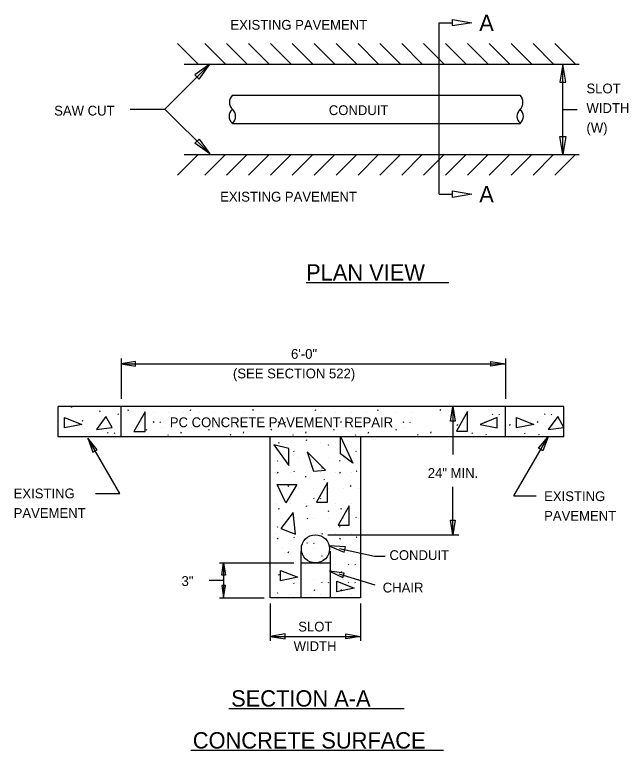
# Model space of a CAD drawing. Extents: x -234.3 to -227.16, y 225.75 to 234.94.
# Drawn here: x -234.204 to -230.444, y 230.43 to 234.938 of the extents above; entities that cross this region are included whole.
import ezdxf

# ---------------------------------------------------------------- set-up
doc = ezdxf.new("R2010")
doc.units = 0
for name, color, linetype in [('Default', 7, 'Continuous'), ('DETL-DIMS', 7, 'Continuous'), ('DETL-LINE', 7, 'Continuous'), ('DETL-NOTE', 7, 'Continuous'), ('DETL-PATT', 7, 'Continuous'), ('DETL-TITL', 7, 'Continuous')]:
    doc.layers.add(name, color=color, linetype=linetype)

msp = doc.modelspace()

# ---------------------------------------------------------------- linework, layer by layer
at = {"layer": 'Default'}
for p, q in [((-233.938, 232.351), (-233.938, 232.536)), ((-233.8555, 232.5297), (-233.8526, 232.5362)), ((-233.6845, 232.5117), (-233.6837, 232.5052)), ((-233.5098, 232.5127), (-233.507, 232.5192)), ((-233.1272, 232.5127), (-233.1243, 232.5192)), ((-232.7446, 232.5127), (-232.7417, 232.5192)), ((-232.3619, 232.5127), (-232.359, 232.5192)), ((-231.9793, 232.5127), (-231.9764, 232.5192)), ((-231.5966, 232.5127), (-231.5938, 232.5192)), ((-230.839, 232.351), (-230.839, 232.536)), ((-233.79, 232.4463), (-233.7871, 232.4528)), ((-233.5717, 232.4926), (-233.5688, 232.4883)), ((-231.2794, 232.491), (-231.2765, 232.4867)), ((-231.2384, 232.4894), (-231.2355, 232.4851)), ((-230.9574, 232.491), (-230.9545, 232.4867)), ((-230.9164, 232.4894), (-230.9135, 232.4851)), ((-233.3552, 232.444), (-233.3523, 232.4397)), ((-233.3142, 232.4424), (-233.3113, 232.4381)), ((-232.9725, 232.444), (-232.9697, 232.4397)), ((-232.9316, 232.4424), (-232.9287, 232.4381)), ((-232.5899, 232.444), (-232.587, 232.4397)), ((-232.5489, 232.4424), (-232.5461, 232.4381)), ((-232.2073, 232.444), (-232.2044, 232.4397)), ((-232.1663, 232.4424), (-232.1634, 232.4381)), ((-231.8246, 232.444), (-231.8217, 232.4397)), ((-231.7837, 232.4424), (-231.7808, 232.4381)), ((-231.4923, 232.4211), (-231.4894, 232.4276)), ((-231.3209, 232.4397), (-231.319, 232.4442)), ((-231.1703, 232.4211), (-231.1674, 232.4276)), ((-230.9998, 232.4377), (-230.997, 232.4442)), ((-233.6354, 232.3776), (-233.6325, 232.3732)), ((-233.5944, 232.3759), (-233.5915, 232.3716)), ((-233.3976, 232.3907), (-233.3948, 232.3972)), ((-233.266, 232.3658), (-233.2631, 232.3614)), ((-233.1855, 232.3742), (-233.1826, 232.3806)), ((-233.015, 232.3907), (-233.0121, 232.3972)), ((-232.8833, 232.3658), (-232.8805, 232.3614)), ((-232.8028, 232.3742), (-232.7999, 232.3806)), ((-232.6324, 232.3907), (-232.6295, 232.3972)), ((-232.5007, 232.3658), (-232.4978, 232.3614)), ((-232.4202, 232.3742), (-232.4173, 232.3806)), ((-232.2497, 232.3907), (-232.2468, 232.3972)), ((-232.1181, 232.3658), (-232.1152, 232.3614)), ((-232.0375, 232.3742), (-232.0347, 232.3806)), ((-231.8671, 232.3907), (-231.8642, 232.3972)), ((-231.7354, 232.3658), (-231.7325, 232.3614)), ((-231.6549, 232.3742), (-231.652, 232.3806)), ((-231.4024, 232.3751), (-231.3995, 232.3708)), ((-231.3174, 232.3673), (-231.3145, 232.363)), ((-231.0804, 232.3751), (-231.0775, 232.3708)), ((-230.9954, 232.3673), (-230.9925, 232.363)), ((-232.5866, 232.3116), (-232.5837, 232.3181)), ((-232.4161, 232.3282), (-232.4132, 232.3346)), ((-232.2844, 232.3032), (-232.2816, 232.2989)), ((-232.4966, 232.2656), (-232.4938, 232.2613)), ((-232.4116, 232.2578), (-232.4088, 232.2535)), ((-232.114, 232.2656), (-232.1111, 232.2613)), ((-232.5961, 232.2067), (-232.5932, 232.2024)), ((-232.2135, 232.2067), (-232.2106, 232.2024)), ((-232.5938, 232.1289), (-232.5909, 232.1354)), ((-232.4939, 232.1429), (-232.4911, 232.1385)), ((-232.3204, 232.1584), (-232.3176, 232.1649)), ((-232.2111, 232.1289), (-232.2082, 232.1354)), ((-232.1113, 232.1429), (-232.1084, 232.1385)), ((-232.4227, 232.1108), (-232.422, 232.1044)), ((-232.31, 232.0918), (-232.3071, 232.0875)), ((-232.5283, 232.0455), (-232.5254, 232.0519)), ((-232.1457, 232.0455), (-232.1428, 232.0519)), ((-232.3736, 231.9768), (-232.3708, 231.9724)), ((-232.3327, 231.9751), (-232.3298, 231.9708)), ((-232.5866, 231.9069), (-232.5837, 231.9134)), ((-232.4161, 231.9234), (-232.4132, 231.9299)), ((-232.2039, 231.9069), (-232.201, 231.9134)), ((-232.2844, 231.8985), (-232.2816, 231.8942)), ((-232.4966, 231.8609), (-232.4938, 231.8565)), ((-232.4116, 231.8531), (-232.4088, 231.8488)), ((-232.114, 231.8609), (-232.1111, 231.8565)), ((-232.5961, 231.802), (-232.5932, 231.7977)), ((-232.2135, 231.802), (-232.2106, 231.7977)), ((-232.5938, 231.7242), (-232.5909, 231.7307)), ((-232.4939, 231.7381), (-232.4911, 231.7338)), ((-232.3204, 231.7537), (-232.3176, 231.7602)), ((-232.2111, 231.7242), (-232.2082, 231.7307)), ((-232.1113, 231.7381), (-232.1084, 231.7338)), ((-232.4145, 231.7029), (-232.4116, 231.6985)), ((-232.3736, 231.7012), (-232.3707, 231.6969)), ((-232.5283, 231.6408), (-232.5254, 231.6472)), ((-232.3253, 231.6246), (-232.3224, 231.6203)), ((-232.1611, 231.5721), (-232.1582, 231.5677)), ((-232.1201, 231.5704), (-232.1172, 231.5661)), ((-232.5866, 231.5022), (-232.5837, 231.5087)), ((-232.2035, 231.5187), (-232.2006, 231.5252)), ((-232.3246, 231.4617), (-232.3217, 231.4574)), ((-232.2836, 231.46), (-232.2807, 231.4557)), ((-232.1611, 231.4617), (-232.1582, 231.4574)), ((-232.1201, 231.46), (-232.1172, 231.4557)), ((-232.4966, 231.4562), (-232.4938, 231.4518)), ((-232.367, 231.4084), (-232.3642, 231.4148)), ((-232.2035, 231.4084), (-232.2006, 231.4148)), ((-232.5961, 231.3973), (-232.5932, 231.393))]:
    msp.add_line(p, q, dxfattribs=at)
at = {"layer": 'DETL-DIMS'}
for p, q in [((-231.6036, 234.8875), (-231.5216, 234.8875)), ((-231.6036, 233.8385), (-231.6036, 234.8875)), ((-233.2846, 234.3595), (-233.0086, 234.6335)), ((-230.8446, 234.0815), (-230.8446, 234.6335)), ((-233.2866, 234.3575), (-233.4966, 234.3575)), ((-233.0086, 234.0855), (-233.2846, 234.3595)), ((-230.7566, 234.3555), (-230.8446, 234.3555)), ((-231.6036, 233.8385), (-231.5216, 233.8385)), ((-233.553, 232.83), (-233.553, 232.584)), ((-231.197, 232.83), (-231.197, 232.584)), ((-233.553, 232.798), (-231.197, 232.798)), ((-231.52, 232.536), (-231.52, 232.242)), ((-233.561, 232.004), (-233.756, 232.342)), ((-231.146, 231.989), (-230.936, 232.351)), ((-231.52, 231.751), (-231.52, 232.045)), ((-233.71, 232.004), (-233.561, 232.004)), ((-231.146, 231.989), (-231.009, 231.989)), ((-232.285, 231.751), (-231.482, 231.751)), ((-232.214, 231.667), (-232, 231.62)), ((-232, 231.62), (-231.934, 231.62)), ((-232.949, 231.578), (-232.493, 231.578)), ((-232.924, 231.578), (-232.924, 231.364)), ((-232.218, 231.511), (-231.997, 231.444)), ((-232.924, 231.471), (-233.013, 231.471)), ((-232.949, 231.364), (-232.675, 231.364)), ((-232.638, 231.33), (-232.638, 231.101)), ((-232.085, 231.33), (-232.085, 231.101)), ((-232.638, 231.128), (-232.085, 231.128))]:
    msp.add_line(p, q, dxfattribs=at)
for points in [[(-231.5216, 234.8685), (-231.5216, 234.9075), (-231.4026, 234.8875)], [(-233.0996, 234.5695), (-233.0736, 234.5435), (-233.0086, 234.6335)], [(-230.8636, 234.5235), (-230.8266, 234.5235), (-230.8446, 234.6335)], [(-233.0996, 234.1495), (-233.0736, 234.1755), (-233.0086, 234.0855)], [(-230.8636, 234.1915), (-230.8266, 234.1915), (-230.8446, 234.0815)], [(-231.5216, 233.8175), (-231.5216, 233.8575), (-231.4026, 233.8375)], [(-233.464, 232.783), (-233.464, 232.813), (-233.553, 232.798)], [(-231.287, 232.783), (-231.287, 232.813), (-231.197, 232.798)], [(-231.505, 232.446), (-231.534, 232.446), (-231.52, 232.536)], [(-233.725, 232.257), (-233.699, 232.272), (-233.756, 232.342)], [(-230.968, 232.266), (-230.994, 232.281), (-230.936, 232.351)], [(-231.534, 231.84), (-231.505, 231.84), (-231.52, 231.751)], [(-232.185, 231.644), (-232.178, 231.676), (-232.279, 231.682)], [(-232.912, 231.503), (-232.936, 231.503), (-232.924, 231.578)], [(-232.194, 231.488), (-232.186, 231.516), (-232.276, 231.528)], [(-232.912, 231.439), (-232.936, 231.439), (-232.924, 231.364)], [(-232.548, 231.113), (-232.548, 231.143), (-232.638, 231.128)], [(-232.175, 231.113), (-232.175, 231.143), (-232.085, 231.128)]]:
    msp.add_lwpolyline(points, close=True, dxfattribs=at)
at = {"layer": 'DETL-LINE'}
for p, q in [((-233.1666, 234.6335), (-230.7446, 234.6335)), ((-232.8706, 234.4435), (-231.1076, 234.4435)), ((-232.8706, 234.2715), (-231.1076, 234.2715)), ((-233.1666, 234.0815), (-230.7446, 234.0815)), ((-230.839, 232.536), (-233.938, 232.536)), ((-233.553, 232.351), (-233.553, 232.536)), ((-231.197, 232.351), (-231.197, 232.536)), ((-230.839, 232.351), (-233.938, 232.351)), ((-232.638, 231.365), (-232.638, 232.351)), ((-232.085, 232.351), (-232.085, 231.365)), ((-232.451, 231.65), (-232.451, 231.365)), ((-232.272, 231.65), (-232.272, 231.365)), ((-232.451, 231.578), (-232.272, 231.578)), ((-232.086, 231.364), (-232.637, 231.364))]:
    msp.add_line(p, q, dxfattribs=at)
msp.add_circle((-232.3615, 231.6646), 0.0864, dxfattribs=at)
for centre, radius, start, end in [((-232.8275, 234.401), 0.0609, 135, 225), ((-231.1504, 234.401), 0.0609, 315, 45), ((-232.8344, 234.3148), 0.0563, 130.035, 229.965), ((-232.907, 234.3148), 0.0564, 310.1735, 49.8265), ((-231.071, 234.3148), 0.0564, 130.1735, 229.8265), ((-231.1436, 234.3148), 0.0563, 310.035, 49.965)]:
    msp.add_arc(centre, radius, start, end, dxfattribs=at)
at = {"layer": 'DETL-PATT'}
for p, q in [((-233.0796, 234.6335), (-233.2066, 234.7605)), ((-232.9136, 234.6335), (-233.0396, 234.7605)), ((-232.7796, 234.6335), (-232.9056, 234.7605)), ((-232.6456, 234.6335), (-232.7716, 234.7605)), ((-232.5106, 234.6335), (-232.6376, 234.7605)), ((-232.3766, 234.6335), (-232.5036, 234.7605)), ((-232.2426, 234.6335), (-232.3696, 234.7605)), ((-232.1086, 234.6335), (-232.2346, 234.7605)), ((-231.9746, 234.6335), (-232.1006, 234.7605)), ((-231.8406, 234.6335), (-231.9666, 234.7605)), ((-231.7066, 234.6335), (-231.8326, 234.7605)), ((-231.5726, 234.6335), (-231.6986, 234.7605)), ((-231.4376, 234.6335), (-231.5646, 234.7605)), ((-231.3036, 234.6335), (-231.4306, 234.7605)), ((-231.1696, 234.6335), (-231.2966, 234.7605)), ((-231.0356, 234.6335), (-231.1616, 234.7605)), ((-230.9016, 234.6335), (-231.0276, 234.7605)), ((-230.7676, 234.6335), (-230.8936, 234.7605)), ((-233.0796, 234.0815), (-233.2066, 233.9545)), ((-232.9136, 234.0815), (-233.0396, 233.9545)), ((-232.7796, 234.0815), (-232.9056, 233.9545)), ((-232.6456, 234.0815), (-232.7716, 233.9545)), ((-232.5106, 234.0815), (-232.6376, 233.9545)), ((-232.3766, 234.0815), (-232.5036, 233.9545)), ((-232.2426, 234.0815), (-232.3696, 233.9545)), ((-232.1086, 234.0815), (-232.2346, 233.9545)), ((-231.9746, 234.0815), (-232.1006, 233.9545)), ((-231.8406, 234.0815), (-231.9666, 233.9545)), ((-231.7066, 234.0815), (-231.8326, 233.9545)), ((-231.5726, 234.0815), (-231.6986, 233.9545)), ((-231.4376, 234.0815), (-231.5646, 233.9545)), ((-231.3036, 234.0815), (-231.4306, 233.9545)), ((-231.1696, 234.0815), (-231.2966, 233.9545)), ((-231.0356, 234.0815), (-231.1616, 233.9545)), ((-230.9016, 234.0815), (-231.0276, 233.9545)), ((-230.7676, 234.0815), (-230.8936, 233.9545)), ((-233.405, 232.504), (-233.474, 232.384)), ((-233.405, 232.384), (-233.405, 232.504)), ((-233.353, 232.503), (-233.353, 232.503)), ((-233.26, 232.503), (-233.26, 232.503)), ((-233.167, 232.503), (-233.167, 232.503)), ((-233.074, 232.503), (-233.074, 232.503)), ((-232.981, 232.503), (-232.981, 232.503)), ((-232.888, 232.503), (-232.888, 232.503)), ((-232.794, 232.503), (-232.794, 232.503)), ((-232.701, 232.503), (-232.701, 232.503)), ((-232.608, 232.503), (-232.608, 232.503)), ((-232.515, 232.503), (-232.515, 232.503)), ((-232.422, 232.503), (-232.422, 232.503)), ((-232.329, 232.503), (-232.329, 232.503)), ((-232.236, 232.503), (-232.236, 232.503)), ((-232.142, 232.503), (-232.142, 232.503)), ((-232.049, 232.503), (-232.049, 232.503)), ((-231.956, 232.503), (-231.956, 232.503)), ((-231.863, 232.503), (-231.863, 232.503)), ((-231.77, 232.503), (-231.77, 232.503)), ((-231.43, 232.506), (-231.498, 232.386)), ((-231.43, 232.386), (-231.43, 232.506)), ((-233.9, 232.469), (-233.794, 232.427)), ((-233.9, 232.406), (-233.9, 232.469)), ((-233.645, 232.476), (-233.703, 232.396)), ((-233.607, 232.408), (-233.645, 232.476)), ((-231.247, 232.469), (-231.353, 232.427)), ((-231.247, 232.406), (-231.247, 232.469)), ((-231.129, 232.469), (-231.023, 232.427)), ((-231.129, 232.406), (-231.129, 232.469)), ((-230.877, 232.476), (-230.935, 232.396)), ((-230.839, 232.408), (-230.877, 232.476)), ((-233.794, 232.427), (-233.9, 232.406)), ((-233.703, 232.396), (-233.607, 232.408)), ((-233.307, 232.41), (-233.307, 232.41)), ((-233.214, 232.41), (-233.214, 232.41)), ((-233.12, 232.41), (-233.12, 232.41)), ((-233.027, 232.41), (-233.027, 232.41)), ((-232.934, 232.41), (-232.934, 232.41)), ((-232.841, 232.41), (-232.841, 232.41)), ((-232.748, 232.41), (-232.748, 232.41)), ((-232.655, 232.41), (-232.655, 232.41)), ((-232.562, 232.41), (-232.562, 232.41)), ((-232.468, 232.41), (-232.468, 232.41)), ((-232.375, 232.41), (-232.375, 232.41)), ((-232.282, 232.41), (-232.282, 232.41)), ((-232.189, 232.41), (-232.189, 232.41)), ((-232.096, 232.41), (-232.096, 232.41)), ((-232.003, 232.41), (-232.003, 232.41)), ((-231.91, 232.41), (-231.91, 232.41)), ((-231.816, 232.41), (-231.816, 232.41)), ((-231.353, 232.427), (-231.247, 232.406)), ((-231.023, 232.427), (-231.129, 232.406)), ((-230.935, 232.396), (-230.839, 232.408)), ((-233.474, 232.384), (-233.405, 232.384)), ((-231.498, 232.386), (-231.43, 232.386)), ((-232.608, 232.317), (-232.608, 232.317)), ((-232.515, 232.317), (-232.515, 232.317)), ((-232.422, 232.317), (-232.422, 232.317)), ((-232.329, 232.317), (-232.329, 232.317)), ((-232.236, 232.317), (-232.236, 232.317)), ((-232.208, 232.352), (-232.133, 232.19)), ((-232.208, 232.246), (-232.208, 232.352)), ((-232.142, 232.317), (-232.142, 232.317)), ((-232.524, 232.28), (-232.616, 232.301)), ((-232.616, 232.301), (-232.524, 232.175)), ((-232.524, 232.175), (-232.524, 232.28)), ((-232.562, 232.224), (-232.562, 232.224)), ((-232.468, 232.224), (-232.468, 232.224)), ((-232.299, 232.147), (-232.413, 232.259)), ((-232.413, 232.259), (-232.374, 232.14)), ((-232.375, 232.224), (-232.375, 232.224)), ((-232.282, 232.224), (-232.282, 232.224)), ((-232.133, 232.19), (-232.208, 232.246)), ((-232.189, 232.224), (-232.189, 232.224)), ((-232.096, 232.224), (-232.096, 232.224)), ((-232.374, 232.14), (-232.299, 232.147)), ((-232.608, 232.13), (-232.608, 232.13)), ((-232.515, 232.13), (-232.515, 232.13)), ((-232.422, 232.13), (-232.422, 232.13)), ((-232.329, 232.13), (-232.329, 232.13)), ((-232.236, 232.13), (-232.236, 232.13)), ((-232.142, 232.13), (-232.142, 232.13)), ((-232.543, 231.946), (-232.596, 232.058)), ((-232.596, 232.058), (-232.475, 232.058)), ((-232.475, 232.058), (-232.543, 231.946)), ((-232.288, 232.07), (-232.356, 231.951)), ((-232.288, 231.951), (-232.288, 232.07)), ((-232.562, 232.037), (-232.562, 232.037)), ((-232.468, 232.037), (-232.468, 232.037)), ((-232.375, 232.037), (-232.375, 232.037)), ((-232.282, 232.037), (-232.282, 232.037)), ((-232.189, 232.037), (-232.189, 232.037)), ((-232.096, 232.037), (-232.096, 232.037)), ((-232.608, 231.944), (-232.608, 231.944)), ((-232.515, 231.944), (-232.515, 231.944)), ((-232.422, 231.944), (-232.422, 231.944)), ((-232.356, 231.951), (-232.288, 231.951)), ((-232.329, 231.944), (-232.329, 231.944)), ((-232.236, 231.944), (-232.236, 231.944)), ((-232.155, 231.929), (-232.223, 231.81)), ((-232.155, 231.81), (-232.155, 231.929)), ((-232.142, 231.944), (-232.142, 231.944)), ((-232.498, 231.888), (-232.574, 231.79)), ((-232.483, 231.755), (-232.498, 231.888)), ((-232.562, 231.851), (-232.562, 231.851)), ((-232.468, 231.851), (-232.468, 231.851)), ((-232.375, 231.851), (-232.375, 231.851)), ((-232.282, 231.851), (-232.282, 231.851)), ((-232.189, 231.851), (-232.189, 231.851)), ((-232.096, 231.851), (-232.096, 231.851)), ((-232.574, 231.79), (-232.483, 231.755)), ((-232.223, 231.81), (-232.155, 231.81)), ((-232.608, 231.758), (-232.608, 231.758)), ((-232.515, 231.758), (-232.515, 231.758)), ((-232.422, 231.758), (-232.422, 231.758)), ((-232.329, 231.758), (-232.329, 231.758)), ((-232.236, 231.758), (-232.236, 231.758)), ((-232.142, 231.758), (-232.142, 231.758)), ((-232.562, 231.664), (-232.562, 231.664)), ((-232.468, 231.664), (-232.468, 231.664)), ((-232.375, 231.664), (-232.375, 231.664)), ((-232.282, 231.664), (-232.282, 231.664)), ((-232.189, 231.664), (-232.189, 231.664)), ((-232.096, 231.664), (-232.096, 231.664)), ((-232.608, 231.571), (-232.608, 231.571)), ((-232.515, 231.571), (-232.515, 231.571)), ((-232.422, 231.571), (-232.422, 231.571)), ((-232.329, 231.571), (-232.329, 231.571)), ((-232.236, 231.571), (-232.236, 231.571)), ((-232.142, 231.571), (-232.142, 231.571)), ((-232.576, 231.469), (-232.576, 231.532)), ((-232.576, 231.532), (-232.47, 231.49)), ((-232.47, 231.49), (-232.576, 231.469)), ((-232.562, 231.478), (-232.562, 231.478)), ((-232.468, 231.478), (-232.468, 231.478)), ((-232.375, 231.478), (-232.375, 231.478)), ((-232.282, 231.478), (-232.282, 231.478)), ((-232.231, 231.466), (-232.124, 231.424)), ((-232.231, 231.402), (-232.231, 231.466)), ((-232.189, 231.478), (-232.189, 231.478)), ((-232.096, 231.478), (-232.096, 231.478)), ((-232.124, 231.424), (-232.231, 231.402)), ((-232.608, 231.385), (-232.608, 231.385)), ((-232.515, 231.385), (-232.515, 231.385)), ((-232.422, 231.385), (-232.422, 231.385)), ((-232.329, 231.385), (-232.329, 231.385)), ((-232.236, 231.385), (-232.236, 231.385)), ((-232.142, 231.385), (-232.142, 231.385))]:
    msp.add_line(p, q, dxfattribs=at)
at = {"layer": 'DETL-TITL'}
for p, q in [((-232.4186, 233.2972), (-231.5441, 233.2972)), ((-232.8928, 230.6866), (-231.8186, 230.6866)), ((-233.1252, 230.4301), (-231.5774, 230.4301))]:
    msp.add_line(p, q, dxfattribs=at)

# ---------------------------------------------------------------- texts
at = {"layer": 'DETL-NOTE'}
for s, height, p in [('A', 0.1, (-231.3576, 234.8375)), ('EXISTING PAVEMENT', 0.06, (-232.8826, 234.8455)), ('SLOT', 0.06, (-230.7006, 234.4555)), ('WIDTH', 0.06, (-230.7006, 234.3355)), ('SAW CUT', 0.06, (-233.9626, 234.3195)), ('CONDUIT', 0.06, (-232.2796, 234.3225)), ('(W)', 0.06, (-230.7006, 234.2155)), ('EXISTING PAVEMENT', 0.06, (-232.9456, 233.7925)), ('A', 0.1, (-231.3576, 233.7875)), ('6\'-0"', 0.06, (-232.511, 232.829)), ('(SEE SECTION 522)', 0.06, (-232.867, 232.709)), ('PC CONCRETE PAVEMENT REPAIR', 0.06, (-233.254, 232.41)), ('24" MIN.', 0.06, (-231.673, 232.099)), ('EXISTING', 0.06, (-234.211, 231.974)), ('EXISTING', 0.06, (-230.96, 231.957)), ('PAVEMENT', 0.06, (-234.211, 231.854)), ('PAVEMENT', 0.06, (-230.96, 231.837)), ('CONDUIT', 0.06, (-231.908, 231.596)), ('3"', 0.06, (-233.182, 231.437)), ('CHAIR', 0.06, (-231.949, 231.397)), ('SLOT', 0.06, (-232.467, 231.158)), ('WIDTH', 0.06, (-232.495, 231.038))]:
    msp.add_text(s, height=height, dxfattribs=at).set_placement(p)
at = {"layer": 'DETL-TITL'}
for s, height, p in [('PLAN VIEW', 0.1, (-232.4186, 233.3085)), ('SECTION A-A', 0.100002, (-232.878, 230.698)), ('CONCRETE SURFACE', 0.100002, (-233.113, 230.441))]:
    msp.add_text(s, height=height, dxfattribs=at).set_placement(p)

doc.saveas('drawing.dxf')
